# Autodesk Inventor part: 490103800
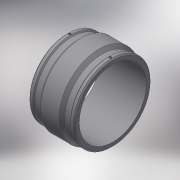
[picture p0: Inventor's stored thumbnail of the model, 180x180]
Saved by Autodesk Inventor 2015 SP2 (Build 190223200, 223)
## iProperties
Created: 2017-06
Part Number: 490103800
Material: Generic
Description: PLASSON COUPLER 800
Document SubType Name: Modeling
Designer: KIM
Mass: 16398.8 g
Surface Area: 10528.4 cm^2
Volume: 16398.8 cm^3
Density: 1 g/cm^3
Appearance: Default
Author: KIM
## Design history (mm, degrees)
derived "490103.ipt"
feature "Solid1::490103.ipt"
tag "TaggingFeature1"
body "Solid1"
other parameters: "d23" = 955, "d24" = 873, "d25" = 135 deg, "d27" = 135 deg, "d35" = 15, "d39" = 0, "d40" = 4, "d41" = 14, "d42" = 0, "d43" = 135 deg, "d44" = 55, "d46" = 6, "d47" = 0, "D_" = 955, "d_2" = 12
